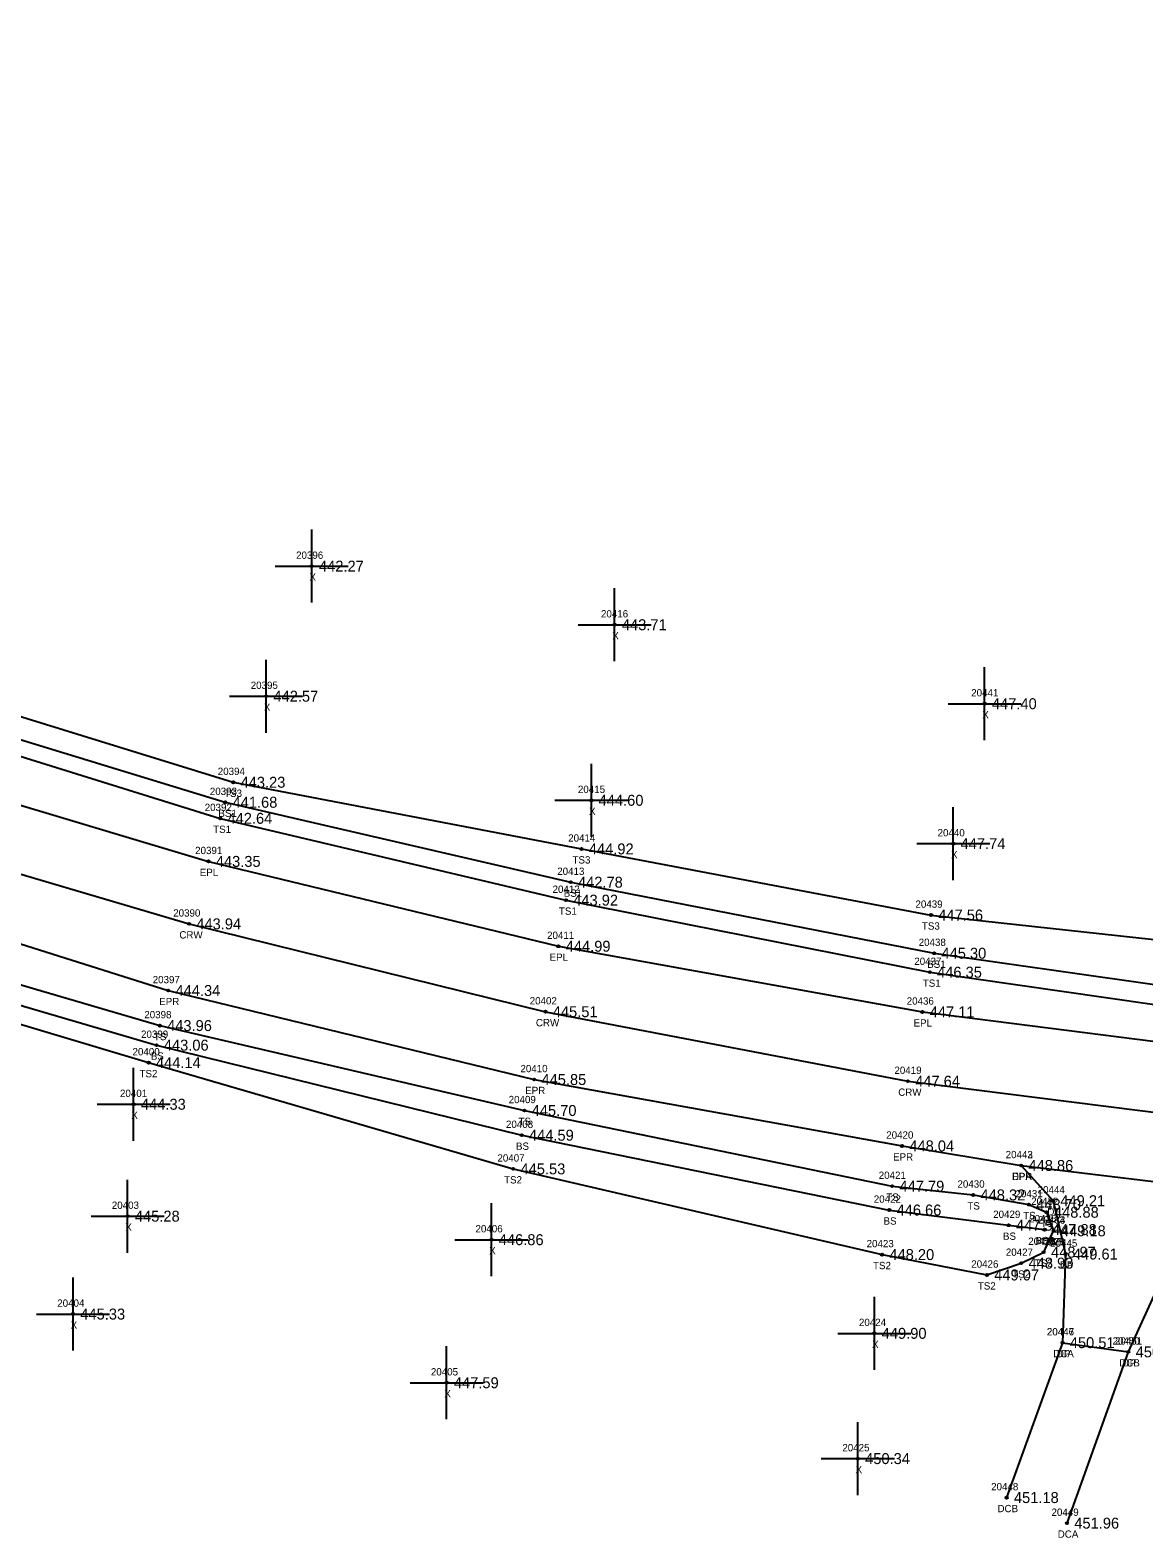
# Model space of a CAD drawing. Extents: x 1810114 to 1811498, y 790790 to 791824.
# Drawn here: x 1811012.6 to 1811165.1, y 791095.2 to 791301.8 of the extents above; entities that cross this region are included whole.
import ezdxf

# ---------------------------------------------------------------- set-up
doc = ezdxf.new("R2010")
doc.units = 0
for name, color, linetype in [('RD_DTM_BkLn1', 7, 'Continuous'), ('RD_DTM_BkLn2', 7, 'Continuous'), ('RD_DTM_BkLn_txCode', 7, 'Continuous'), ('RD_EX_Conc', 7, 'Continuous'), ('RD_EX_Conc_txCode', 7, 'Continuous'), ('RD_EX_Driveway', 7, 'Continuous'), ('RD_EX_Driveway_txCode', 7, 'Continuous'), ('RD_EX_Misc', 7, 'Continuous'), ('RD_EX_Misc_txCode', 7, 'Continuous'), ('RD_EX_Road', 7, 'Continuous'), ('RD_EX_Road_txCode', 7, 'Continuous'), ('RD_EX_TX_Conc_ELEV', 7, 'Continuous'), ('RD_EX_TX_Driveway_ELEV', 7, 'Continuous'), ('RD_EX_TX_Misc_ELEV', 7, 'Continuous'), ('RD_EX_TX_Road_ELEV', 7, 'Continuous'), ('RD_HC_Survey_ELEV', 7, 'Continuous'), ('RD_HC_Survey_txCode', 7, 'Continuous'), ('RD_SMD_Locator', 7, 'Continuous')]:
    doc.layers.add(name, color=color, linetype=linetype)

msp = doc.modelspace()

# ---------------------------------------------------------------- linework, layer by layer
at = {"layer": 'RD_DTM_BkLn1'}
msp.add_lwpolyline([(1810803.51, 791274.51), (1810847.74, 791252.12), (1810893.26, 791230.1), (1810939.59, 791211.03), (1810986.75, 791193.39), (1811034.36, 791179.34), (1811083.17, 791167.31), (1811132.79, 791157.79), (1811182.67, 791151.51), (1811232.87, 791147.29), (1811282.59, 791145.39), (1811332.65, 791144.69), (1811383.13, 791143.44), (1811433.19, 791141.72), (1811483.07, 791139)], dxfattribs=at)
at = {"layer": 'RD_DTM_BkLn2'}
for points in [[(1810797.71, 791296.87), (1810806.65, 791301.43), (1810818.39, 791301.77), (1810860.19, 791276.21), (1810904.39, 791251.18), (1810946.65, 791228.17), (1810992.83, 791210.21), (1811039.32, 791196), (1811086.62, 791185.05), (1811136.39, 791175.32), (1811184.54, 791168.49), (1811233.77, 791164.27), (1811283.33, 791162.64), (1811288.69, 791162.37)], [(1810810.94, 791288.35), (1810813.31, 791289.84), (1810816.6, 791289.48), (1810819.25, 791288.81), (1810826.35, 791283.83), (1810857.88, 791269.62), (1810901.46, 791245.99), (1810945.33, 791226.23), (1810992.32, 791208.19), (1811038.63, 791193.8), (1811085.97, 791182.59), (1811135.79, 791172.72), (1811184.32, 791165.75), (1811233.45, 791162.61), (1811282.83, 791159.28), (1811288.11, 791158.81), (1811290.26, 791160.7), (1811291.15, 791162.18)], [(1810798.82, 791261.28), (1810799.43, 791259.17), (1810802.84, 791255.6), (1810808.45, 791252.93), (1810841.34, 791238.85), (1810887.19, 791215.38), (1810933.38, 791195.46), (1810982.02, 791179.58), (1811030.36, 791165.41), (1811080.28, 791153.78), (1811130.64, 791143.41), (1811141.73, 791142.21), (1811149.36, 791140.89), (1811151.79, 791139.84), (1811152.74, 791137.29)], [(1810783.34, 791255.23), (1810786.99, 791254.41), (1810790.75, 791251.26), (1810797.13, 791248.85), (1810804.71, 791244.89), (1810838.03, 791232.12), (1810885, 791211), (1810932.8, 791192.41), (1810981.62, 791176.86), (1811029.91, 791162.73), (1811079.91, 791150.39), (1811130.24, 791140.14), (1811146.59, 791138.06), (1811151.52, 791137.46)], [(1810948.03, 791229.57), (1810994, 791213.09), (1811040.42, 791198.74), (1811088.11, 791189.61), (1811135.95, 791180.55), (1811184.97, 791175.18), (1811234.87, 791170.81), (1811283.91, 791165.94), (1811289.01, 791164.74), (1811290.58, 791163.58), (1811291.15, 791162.18)], [(1810883.83, 791207.75), (1810930.73, 791188.17), (1810980.88, 791174.68), (1811028.83, 791160.33), (1811078.75, 791145.78), (1811129.26, 791134.04), (1811143.61, 791131.25), (1811148.31, 791132.87), (1811151.39, 791134.37), (1811152.74, 791137.29)]]:
    msp.add_lwpolyline(points, dxfattribs=at)
at = {"layer": 'RD_EX_Conc'}
for p, q in [((1811153.96, 791121.97), (1811146.31, 791100.75)), ((1811154.58, 791097.25), (1811162.98, 791120.71))]:
    msp.add_line(p, q, dxfattribs=at)
at = {"layer": 'RD_EX_Driveway'}
msp.add_lwpolyline([(1811148.3, 791146.24), (1811152.67, 791141.42), (1811154.39, 791134.11), (1811153.96, 791121.97), (1811162.98, 791120.71), (1811167.45, 791130.53), (1811170.78, 791138.5), (1811177.02, 791142.75)], dxfattribs=at)
at = {"layer": 'RD_EX_Misc'}
for p, q in [((1811051.16, 791223.35), (1811051.16, 791233.35)), ((1811046.16, 791228.35), (1811056.16, 791228.35)), ((1811092.63, 791215.32), (1811092.63, 791225.32)), ((1811087.63, 791220.32), (1811097.63, 791220.32)), ((1811044.92, 791205.53), (1811044.92, 791215.53)), ((1811143.3, 791204.5), (1811143.3, 791214.5)), ((1811039.92, 791210.53), (1811049.92, 791210.53)), ((1811138.3, 791209.5), (1811148.3, 791209.5)), ((1811089.45, 791191.27), (1811089.45, 791201.27)), ((1811084.45, 791196.27), (1811094.45, 791196.27)), ((1811139.01, 791185.33), (1811139.01, 791195.33)), ((1811134.01, 791190.33), (1811144.01, 791190.33)), ((1811026.78, 791149.63), (1811026.78, 791159.63)), ((1811021.78, 791154.63), (1811031.78, 791154.63)), ((1811025.95, 791134.3), (1811025.95, 791144.3)), ((1811075.78, 791131.08), (1811075.78, 791141.08)), ((1811020.95, 791139.3), (1811030.95, 791139.3)), ((1811070.78, 791136.08), (1811080.78, 791136.08)), ((1811018.48, 791120.89), (1811018.48, 791130.89)), ((1811128.21, 791118.25), (1811128.21, 791128.25)), ((1811013.48, 791125.89), (1811023.48, 791125.89)), ((1811123.21, 791123.25), (1811133.21, 791123.25)), ((1811069.63, 791111.48), (1811069.63, 791121.48)), ((1811064.63, 791116.48), (1811074.63, 791116.48)), ((1811125.94, 791101.09), (1811125.94, 791111.09)), ((1811120.94, 791106.09), (1811130.94, 791106.09))]:
    msp.add_line(p, q, dxfattribs=at)
at = {"layer": 'RD_EX_Road'}
for points in [[(1810807.88, 791282.84), (1810852, 791259.68), (1810897.52, 791238.67), (1810942.78, 791219.24), (1810989.92, 791202.01), (1811037.03, 791187.9), (1811084.94, 791176.28), (1811134.78, 791167.28), (1811183.92, 791161.02), (1811232.9, 791156.58), (1811282.68, 791154.92), (1811285.25, 791154.67), (1811313.54, 791153.96), (1811332.83, 791153.68), (1811383.78, 791152.53), (1811433.81, 791151.61), (1811483.97, 791148.18)], [(1810799.46, 791266.97), (1810843.53, 791244.35), (1810889.8, 791222.88), (1810936.32, 791202.72), (1810983.79, 791185.28), (1811031.51, 791170.21), (1811081.62, 791158.02), (1811131.99, 791148.92), (1811148.3, 791146.24), (1811177.02, 791142.75), (1811182.52, 791142.23), (1811232.71, 791137.62), (1811281.86, 791136.25), (1811332.25, 791135.72), (1811383.92, 791134.19), (1811422.24, 791132.82), (1811433.21, 791132.2), (1811452.43, 791131.25), (1811482.29, 791129.59)]]:
    msp.add_lwpolyline(points, dxfattribs=at)
at = {"layer": 'RD_SMD_Locator'}
for centre in [(1811051.16, 791228.35), (1811092.63, 791220.32), (1811044.92, 791210.53), (1811143.3, 791209.5), (1811040.42, 791198.74), (1811039.32, 791196), (1811089.45, 791196.27), (1811038.63, 791193.8), (1811088.11, 791189.61), (1811139.01, 791190.33), (1811037.03, 791187.9), (1811086.62, 791185.05), (1811085.97, 791182.59), (1811135.95, 791180.55), (1811034.36, 791179.34), (1811084.94, 791176.28), (1811136.39, 791175.32), (1811135.79, 791172.72), (1811031.51, 791170.21), (1811083.17, 791167.31), (1811134.78, 791167.28), (1811030.36, 791165.41), (1811029.91, 791162.73), (1811028.83, 791160.33), (1811081.62, 791158.02), (1811132.79, 791157.79), (1811026.78, 791154.63), (1811080.28, 791153.78), (1811079.91, 791150.39), (1811131.99, 791148.92), (1811078.75, 791145.78), (1811148.3, 791146.24), (1811148.3, 791146.24), (1811130.64, 791143.41), (1811141.73, 791142.21), (1811149.36, 791140.89), (1811152.67, 791141.42), (1811025.95, 791139.3), (1811130.24, 791140.14), (1811151.79, 791139.84), (1811146.59, 791138.06), (1811151.52, 791137.46), (1811152.74, 791137.29), (1811152.74, 791137.29), (1811075.78, 791136.08), (1811129.26, 791134.04), (1811148.31, 791132.87), (1811151.39, 791134.37), (1811154.39, 791134.11), (1811143.61, 791131.25), (1811018.48, 791125.89), (1811128.21, 791123.25), (1811153.96, 791121.97), (1811153.96, 791121.97), (1811162.98, 791120.71), (1811162.98, 791120.71), (1811069.63, 791116.48), (1811125.94, 791106.09), (1811146.31, 791100.75), (1811154.58, 791097.25)]:
    msp.add_circle(centre, 0.15, dxfattribs=at)

# ---------------------------------------------------------------- texts
at = {"layer": 'RD_DTM_BkLn_txCode'}
for s, p in [('20394', (1811038.3, 791199.74)), ('20393', (1811037.21, 791197)), ('TS3', (1811039.17, 791196.74)), ('20392', (1811036.51, 791194.8)), ('BS1', (1811038.38, 791194)), ('TS1', (1811037.67, 791191.8)), ('20414', (1811086.28, 791190.61)), ('TS3', (1811086.87, 791187.61)), ('20413', (1811084.78, 791186.05)), ('20412', (1811084.14, 791183.59)), ('BS1', (1811085.67, 791183.05)), ('20439', (1811133.83, 791181.55)), ('TS1', (1811085.01, 791180.59)), ('TS3', (1811134.71, 791178.55)), ('20438', (1811134.27, 791176.32)), ('20437', (1811133.67, 791173.72)), ('BS1', (1811135.44, 791173.32)), ('TS1', (1811134.83, 791170.72)), ('20398', (1811028.24, 791166.41)), ('20399', (1811027.79, 791163.73)), ('TS', (1811029.56, 791163.41)), ('20400', (1811026.63, 791161.33)), ('BS', (1811029.13, 791160.73)), ('TS2', (1811027.58, 791158.33)), ('20409', (1811078.13, 791154.78)), ('20408', (1811077.76, 791151.39)), ('TS', (1811079.49, 791151.78)), ('BS', (1811079.13, 791148.39)), ('20407', (1811076.59, 791146.78)), ('20421', (1811128.8, 791144.41)), ('TS2', (1811077.5, 791143.78)), ('20430', (1811139.58, 791143.21)), ('20422', (1811128.12, 791141.14)), ('TS', (1811129.84, 791141.41)), ('TS', (1811140.94, 791140.21)), ('20431', (1811147.53, 791141.89)), ('20432', (1811149.67, 791140.84)), ('BS', (1811129.46, 791138.14)), ('20429', (1811144.47, 791139.06)), ('TS', (1811148.57, 791138.89)), ('20435', (1811149.4, 791138.46)), ('20433', (1811150.62, 791138.29)), ('20434', (1811150.62, 791138.29)), ('BS', (1811145.81, 791136.06)), ('TS', (1811151, 791137.84)), ('20423', (1811127.14, 791135.04)), ('20427', (1811146.2, 791133.87)), ('20428', (1811149.27, 791135.37)), ('BSB', (1811150.26, 791135.46)), ('TS2B', (1811151.02, 791135.29)), ('TSB', (1811151.47, 791135.29)), ('TS2', (1811128.02, 791132.04)), ('20426', (1811141.47, 791132.25)), ('TS2', (1811150.15, 791132.37)), ('TS2', (1811147.07, 791130.87)), ('TS2', (1811142.37, 791129.25))]:
    msp.add_text(s, height=1, dxfattribs=at).set_placement(p)
at = {"layer": 'RD_EX_Conc_txCode'}
for s, p in [('20447', (1811151.84, 791122.97)), ('20450', (1811160.82, 791121.71)), ('DCA', (1811152.69, 791119.97)), ('DCB', (1811161.73, 791118.71)), ('20448', (1811144.19, 791101.75)), ('DCB', (1811145.06, 791098.75)), ('20449', (1811152.46, 791098.25)), ('DCA', (1811153.31, 791095.25))]:
    msp.add_text(s, height=1, dxfattribs=at).set_placement(p)
at = {"layer": 'RD_EX_Driveway_txCode'}
for s, p in [('20443', (1811146.18, 791147.24)), ('DPA', (1811147.03, 791144.24)), ('20444', (1811150.56, 791142.42)), ('DP', (1811151.89, 791139.42)), ('20445', (1811152.27, 791135.11)), ('DP', (1811153.61, 791132.11)), ('20446', (1811151.82, 791122.97)), ('20451', (1811161.15, 791121.71)), ('DP', (1811153.18, 791119.97)), ('DP', (1811162.2, 791118.71))]:
    msp.add_text(s, height=1, dxfattribs=at).set_placement(p)
at = {"layer": 'RD_EX_Misc_txCode'}
for s, p in [('20396', (1811049.02, 791229.35)), ('X', (1811050.85, 791226.35)), ('20416', (1811090.77, 791221.32)), ('X', (1811092.32, 791218.32)), ('20395', (1811042.81, 791211.53)), ('20441', (1811141.46, 791210.5)), ('X', (1811044.61, 791208.53)), ('X', (1811142.98, 791207.5)), ('20415', (1811087.61, 791197.27)), ('X', (1811089.13, 791194.27)), ('20440', (1811136.86, 791191.33)), ('X', (1811138.7, 791188.33)), ('20401', (1811024.91, 791155.63)), ('X', (1811026.46, 791152.63)), ('20403', (1811023.79, 791140.3)), ('X', (1811025.64, 791137.3)), ('20406', (1811073.59, 791137.08)), ('X', (1811075.46, 791134.08)), ('20404', (1811016.32, 791126.89)), ('X', (1811018.16, 791123.89)), ('20424', (1811126.09, 791124.25)), ('X', (1811127.89, 791121.25)), ('20405', (1811067.48, 791117.48)), ('X', (1811069.32, 791114.48)), ('20425', (1811123.82, 791107.09)), ('X', (1811125.63, 791104.09))]:
    msp.add_text(s, height=1, dxfattribs=at).set_placement(p)
at = {"layer": 'RD_EX_Road_txCode'}
for s, p in [('20391', (1811035.2, 791188.9)), ('EPL', (1811035.83, 791185.9)), ('20411', (1811083.39, 791177.28)), ('EPL', (1811083.73, 791174.28)), ('20397', (1811029.39, 791171.21)), ('EPR', (1811030.28, 791168.21)), ('20436', (1811132.63, 791168.28)), ('EPL', (1811133.57, 791165.28)), ('20410', (1811079.74, 791159.02)), ('EPR', (1811080.39, 791156.02)), ('20420', (1811129.83, 791149.92)), ('EPR', (1811130.76, 791146.92)), ('20442', (1811146.18, 791147.24)), ('EPR', (1811147.07, 791144.24))]:
    msp.add_text(s, height=1, dxfattribs=at).set_placement(p)
at = {"layer": 'RD_EX_TX_Conc_ELEV'}
for s, p in [('450.51', (1811154.96, 791121.22)), ('450.93', (1811163.98, 791119.96)), ('451.18', (1811147.31, 791100)), ('451.96', (1811155.58, 791096.5))]:
    msp.add_text(s, height=1.5, dxfattribs=at).set_placement(p)
at = {"layer": 'RD_EX_TX_Driveway_ELEV'}
for s, p in [('448.86', (1811149.3, 791145.49)), ('449.21', (1811153.67, 791140.67)), ('449.61', (1811155.39, 791133.36)), ('450.51', (1811154.96, 791121.22)), ('450.93', (1811163.98, 791119.96))]:
    msp.add_text(s, height=1.5, dxfattribs=at).set_placement(p)
at = {"layer": 'RD_EX_TX_Misc_ELEV'}
for s, p in [('442.27', (1811052.16, 791227.6)), ('443.71', (1811093.63, 791219.57)), ('442.57', (1811045.92, 791209.78)), ('447.40', (1811144.3, 791208.75)), ('443.23', (1811041.42, 791197.99)), ('441.68', (1811040.32, 791195.25)), ('444.60', (1811090.45, 791195.52)), ('442.64', (1811039.63, 791193.05)), ('447.74', (1811140.01, 791189.58)), ('444.92', (1811089.11, 791188.86)), ('442.78', (1811087.62, 791184.3)), ('443.92', (1811086.97, 791181.84)), ('447.56', (1811136.95, 791179.8)), ('445.30', (1811137.39, 791174.57)), ('446.35', (1811136.79, 791171.97)), ('443.96', (1811031.36, 791164.66)), ('443.06', (1811030.91, 791161.98)), ('444.14', (1811029.83, 791159.58)), ('444.33', (1811027.78, 791153.88)), ('445.70', (1811081.28, 791153.03)), ('444.59', (1811080.91, 791149.64)), ('445.53', (1811079.75, 791145.03)), ('447.79', (1811131.64, 791142.66)), ('448.32', (1811142.73, 791141.46)), ('448.70', (1811150.36, 791140.14)), ('445.28', (1811026.95, 791138.55)), ('446.66', (1811131.24, 791139.39)), ('448.88', (1811152.79, 791139.09)), ('446.86', (1811076.78, 791135.33)), ('447.52', (1811147.59, 791137.31)), ('447.88', (1811152.52, 791136.71)), ('449.18', (1811153.74, 791136.54)), ('449.18', (1811153.74, 791136.54)), ('448.20', (1811130.26, 791133.29)), ('448.97', (1811152.39, 791133.62)), ('448.93', (1811149.31, 791132.12)), ('449.07', (1811144.61, 791130.5)), ('445.33', (1811019.48, 791125.14)), ('449.90', (1811129.21, 791122.5)), ('447.59', (1811070.63, 791115.73)), ('450.34', (1811126.94, 791105.34))]:
    msp.add_text(s, height=1.5, dxfattribs=at).set_placement(p)
at = {"layer": 'RD_EX_TX_Road_ELEV'}
for s, p in [('443.35', (1811038.03, 791187.15)), ('444.99', (1811085.94, 791175.53)), ('444.34', (1811032.51, 791169.46)), ('447.11', (1811135.78, 791166.53)), ('445.85', (1811082.62, 791157.27)), ('448.04', (1811132.99, 791148.17)), ('448.86', (1811149.3, 791145.49))]:
    msp.add_text(s, height=1.5, dxfattribs=at).set_placement(p)
at = {"layer": 'RD_HC_Survey_ELEV'}
for s, p in [('443.94', (1811035.36, 791178.59)), ('445.51', (1811084.17, 791166.56)), ('447.64', (1811133.79, 791157.04))]:
    msp.add_text(s, height=1.5, dxfattribs=at).set_placement(p)
at = {"layer": 'RD_HC_Survey_txCode'}
for s, p in [('20390', (1811032.2, 791180.34)), ('CRW', (1811033.04, 791177.34)), ('20402', (1811081.01, 791168.31)), ('CRW', (1811081.86, 791165.31)), ('20419', (1811130.95, 791158.79)), ('CRW', (1811131.47, 791155.79))]:
    msp.add_text(s, height=1, dxfattribs=at).set_placement(p)

doc.saveas('drawing.dxf')
